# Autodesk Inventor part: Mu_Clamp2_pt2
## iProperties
Shininess: 64.0
Length Units: 11272
Angle Units: 11279
Time Units: 11290
Mass Units: 11286
Length Display Precision: 3
Angle Display Precision: 2
Compacted: True
Part Number: Mu_Clamp2_pt2
Document SubType Name: Modeling
Created: 2004-08
Designer: John Blackburn
Material: Aluminum-6061
Manufacturer: Standard
Standards Organization: Custom
Density: 0.0
Volumn: 0.0
Area: 0.0
PropertySet Name: Model Information
Control State: 0
Master: False
Checked Out: False
Author: John Blackburn
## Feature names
1. Extrusion1
2. Split1
